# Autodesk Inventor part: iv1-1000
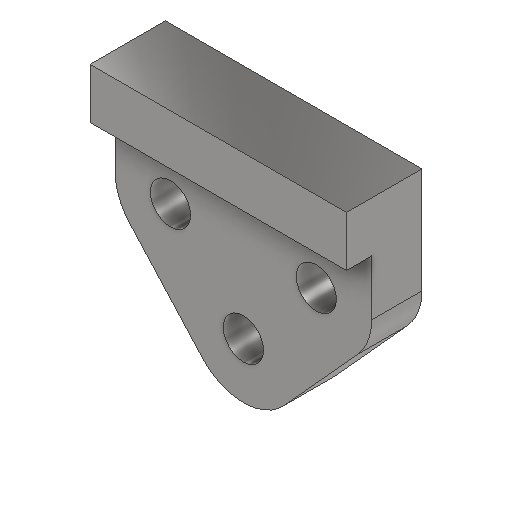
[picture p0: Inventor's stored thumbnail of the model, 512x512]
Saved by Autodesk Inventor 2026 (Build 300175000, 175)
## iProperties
Created: 2022-01
Part Number: iv1-1000
Material: Steel, Mild
Document SubType Name: Modeling
Designer: Lars Bertram Pedersen
Density: 7.85 g/cm^3
Appearance: Semi-Polished
Author: Lars Bertram Pedersen
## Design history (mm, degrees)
sketch "Sketch1"
  geometry: L1 (-51, 0)-(51, 0); L2 (51, 0)-(51, -42); L3 (45.302, -56.773)-(16.302, -88.773); L4 (-16.302, -88.773)-(-45.302, -56.773); L5 (-51, -42)-(-51, 0); C1 r 8 at (-29, -42); C2 r 8 at (29, -42); C3 r 8 at (0, -74); A1 r 22 centre (-29, -42) between (-51, -42) and (-45.302, -56.773); A2 r 22 centre (29, -42) between (45.302, -56.773) and (51, -42); A3 r 22 centre (0, -74) between (-16.302, -88.773) and (16.302, -88.773); 2 further points
  constraints: 10 end point, 6 centre point, 6 point on circle, 6 tangent, 4 coincident, 4 equal radius, 2 parallel, 1 horizontal, 1 midpoint, 1 perpendicular, 1 vertical alignment
  dimensions: "d0" = 102 distance of L1.start L1.end; "d1" = 22 radius of A1 (derived); "d2" = 42 distance from line of A1.centre L1; "d3" = 32 vertical distance of A3.centre A1.centre; "d4" = 16 diameter of C3
extrude "Extrusion1" new body sketch "Sketch1" distance "d5" = 20; taper "d6" = 0 deg
sketch "Sketch2"
  geometry: L1 (-51, 0)-(-51, -42) reference; L2 (51, 0)-(-51, 0) reference; L3 (51, -42)-(51, 0) reference; L4 (-51, -20)-(51, -20); 1 further point
  constraints: 2 end point, 2 point on line, 1 perpendicular
  dimensions: "d7" = 20 distance between parallel lines of L4 L2
extrude "Extrusion2" join sketch "Sketch2" distance "d8" = 10; taper "d9" = 0 deg
body "Solid1"
